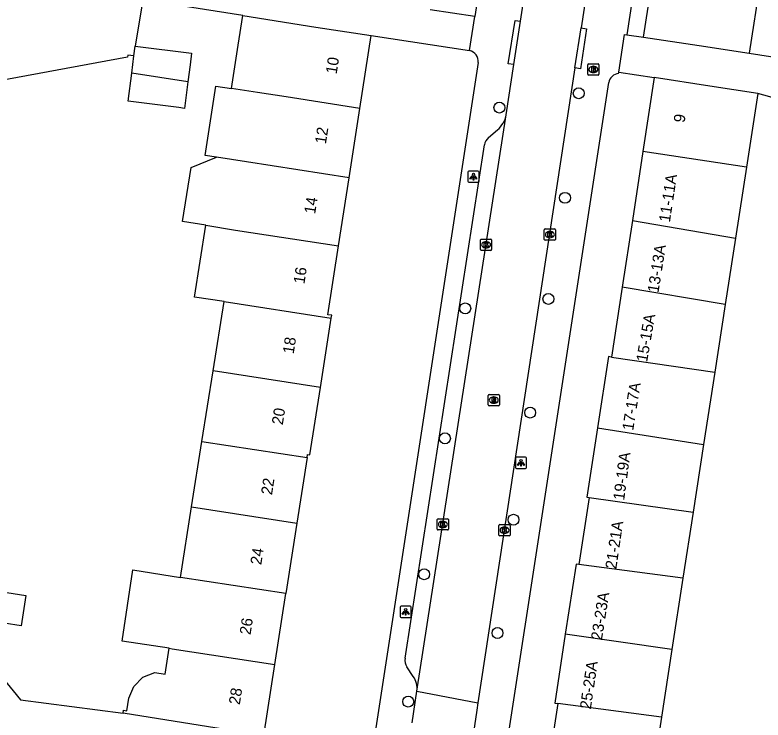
# Model space of a CAD drawing. Extents: x 161486 to 162249, y 379484 to 380829.
# Drawn here: x 162088.8 to 162155.5, y 380629.2 to 380692 of the extents above; entities that cross this region are included whole.
import ezdxf

# ---------------------------------------------------------------- set-up
doc = ezdxf.new("R2010")
doc.units = 0
for name, color, linetype in [('IMGEO_Boom', 7, 'Continuous'), ('IMGEO_Brandkraan', 7, 'Continuous'), ('IMGEO_Kolk', 7, 'Continuous'), ('IMGEO_Lichtpunt', 7, 'Continuous'), ('IMGEO_Pand', 7, 'Continuous'), ('IMGEO_Pand_nummerreeks', 7, 'Continuous'), ('IMGEO_Rijbaan_lokaal_open', 7, 'Continuous'), ('IMGEO_Rioolput', 7, 'Continuous'), ('IMGEO_Voetpad_open', 7, 'Continuous')]:
    doc.layers.add(name, color=color, linetype=linetype)

msp = doc.modelspace()

# ---------------------------------------------------------------- linework, layer by layer
at = {"layer": 'IMGEO_Boom'}
for centre in [(162139.097, 380685.045), (162132.026, 380683.767), (162137.87, 380675.72), (162136.396, 380666.708), (162128.975, 380665.857), (162134.768, 380656.575), (162127.167, 380654.275), (162133.28, 380647.015), (162125.315, 380642.155), (162131.855, 380636.916), (162123.892, 380630.805)]:
    msp.add_circle(centre, 0.489, dxfattribs=at)
at = {"layer": 'IMGEO_Brandkraan'}
for p, q in [((162139.9, 380686.741), (162139.9, 380687.593)), ((162139.975, 380687.667), (162140.827, 380687.667)), ((162140.388, 380687.447), (162140.413, 380687.447)), ((162140.901, 380687.593), (162140.901, 380686.741)), ((162140.827, 380686.667), (162139.975, 380686.667)), ((162140.411, 380686.887), (162140.386, 380686.887))]:
    msp.add_line(p, q, dxfattribs=at)
for points in [[(162139.9, 380686.741), (162139.9, 380687.593)], [(162139.975, 380687.667), (162140.827, 380687.667)], [(162140.248, 380687.367), (162140.248, 380686.967), (162140.461, 380686.967)], [(162140.479, 380687.367), (162140.248, 380687.367)], [(162140.427, 380687.286), (162140.373, 380687.286), (162140.373, 380687.21)], [(162140.373, 380687.21), (162140.426, 380687.21)], [(162140.901, 380687.593), (162140.901, 380686.741)], [(162140.827, 380686.667), (162139.975, 380686.667)], [(162140.435, 380687.134), (162140.373, 380687.134), (162140.373, 380687.053)], [(162140.373, 380687.053), (162140.435, 380687.053)]]:
    msp.add_lwpolyline(points, dxfattribs=at)
for centre, radius, start, end in [((162139.977, 380687.591), 0.0765, 91.55205, 178.44795), ((162139.977, 380687.591), 0.0765, 91.55205, 178.44795), ((162140.428, 380687.248), 0.0379, 267.82845, 90.93552), ((162140.483, 380687.222), 0.145, 59.4692, 91.53667), ((162140.508, 380687.269), 0.0922, 285.51372, 58.15012), ((162140.825, 380687.591), 0.0765, 1.55205, 88.44795), ((162140.825, 380687.591), 0.0765, 1.55205, 88.44795), ((162139.977, 380686.743), 0.0765, 181.55205, 268.44795), ((162139.977, 380686.743), 0.0765, 181.55205, 268.44795), ((162140.436, 380687.093), 0.0404, 269.87594, 90.50774), ((162140.467, 380687.218), 0.251, 268.66757, 293.53466), ((162140.513, 380687.077), 0.105, 301.31148, 78.98903), ((162140.825, 380686.743), 0.0765, 271.55205, 358.44795), ((162140.825, 380686.743), 0.0765, 271.55205, 358.44795)]:
    msp.add_arc(centre, radius, start, end, dxfattribs=at)
for centre, major_axis, ratio, start_param, end_param in [((162140.387, 380687.167), (-0.387, 0.002), 0.722429, 4.712389, 7.853982), ((162140.412, 380687.167), (-0.39, 0.002), 0.717154, 1.570796, 4.712389)]:
    msp.add_ellipse(centre, major_axis=major_axis, ratio=ratio, start_param=start_param, end_param=end_param, dxfattribs=at)
at = {"layer": 'IMGEO_Kolk'}
for p, q in [((162136.024, 380672.017), (162136.024, 380672.869)), ((162136.099, 380672.943), (162136.951, 380672.943)), ((162136.512, 380672.723), (162136.537, 380672.723)), ((162137.025, 380672.869), (162137.025, 380672.017)), ((162130.332, 380671.109), (162130.332, 380671.961)), ((162130.407, 380672.035), (162131.259, 380672.035)), ((162131.333, 380671.961), (162131.333, 380671.109)), ((162136.951, 380671.943), (162136.099, 380671.943)), ((162136.535, 380672.163), (162136.51, 380672.163)), ((162130.843, 380671.255), (162130.818, 380671.255)), ((162130.82, 380671.815), (162130.845, 380671.815)), ((162131.259, 380671.035), (162130.407, 380671.035)), ((162126.482, 380646.178), (162126.482, 380647.03)), ((162126.557, 380647.104), (162127.409, 380647.104)), ((162126.97, 380646.884), (162126.995, 380646.884)), ((162127.483, 380647.03), (162127.483, 380646.178)), ((162131.979, 380645.656), (162131.979, 380646.508)), ((162132.054, 380646.582), (162132.906, 380646.582)), ((162132.98, 380646.508), (162132.98, 380645.656)), ((162127.409, 380646.104), (162126.557, 380646.104)), ((162126.993, 380646.324), (162126.968, 380646.324)), ((162132.467, 380646.362), (162132.492, 380646.362)), ((162132.906, 380645.582), (162132.054, 380645.582)), ((162132.49, 380645.802), (162132.465, 380645.802))]:
    msp.add_line(p, q, dxfattribs=at)
for points in [[(162136.024, 380672.017), (162136.024, 380672.869)], [(162136.099, 380672.943), (162136.951, 380672.943)], [(162136.345, 380672.643), (162136.468, 380672.643), (162136.468, 380672.492), (162136.598, 380672.643), (162136.762, 380672.643), (162136.616, 380672.492), (162136.769, 380672.243), (162136.617, 380672.243), (162136.532, 380672.407), (162136.468, 380672.34), (162136.468, 380672.243), (162136.345, 380672.243), (162136.345, 380672.643)], [(162137.025, 380672.869), (162137.025, 380672.017)], [(162130.332, 380671.109), (162130.332, 380671.961)], [(162130.407, 380672.035), (162131.259, 380672.035)], [(162131.333, 380671.961), (162131.333, 380671.109)], [(162136.951, 380671.943), (162136.099, 380671.943)], [(162130.653, 380671.735), (162130.776, 380671.735), (162130.776, 380671.584), (162130.906, 380671.735), (162131.07, 380671.735), (162130.924, 380671.584), (162131.077, 380671.335), (162130.925, 380671.335), (162130.84, 380671.499), (162130.776, 380671.432), (162130.776, 380671.335), (162130.653, 380671.335), (162130.653, 380671.735)], [(162131.259, 380671.035), (162130.407, 380671.035)], [(162126.482, 380646.178), (162126.482, 380647.03)], [(162126.557, 380647.104), (162127.409, 380647.104)], [(162126.803, 380646.804), (162126.926, 380646.804), (162126.926, 380646.653), (162127.056, 380646.804), (162127.22, 380646.804), (162127.074, 380646.653), (162127.227, 380646.404), (162127.075, 380646.404), (162126.99, 380646.568), (162126.926, 380646.501), (162126.926, 380646.404), (162126.803, 380646.404), (162126.803, 380646.804)], [(162127.483, 380647.03), (162127.483, 380646.178)], [(162131.979, 380645.656), (162131.979, 380646.508)], [(162132.054, 380646.582), (162132.906, 380646.582)], [(162132.98, 380646.508), (162132.98, 380645.656)], [(162127.409, 380646.104), (162126.557, 380646.104)], [(162132.3, 380646.282), (162132.423, 380646.282), (162132.423, 380646.131), (162132.553, 380646.282), (162132.717, 380646.282), (162132.571, 380646.131), (162132.724, 380645.882), (162132.572, 380645.882), (162132.487, 380646.046), (162132.423, 380645.979), (162132.423, 380645.882), (162132.3, 380645.882), (162132.3, 380646.282)], [(162132.906, 380645.582), (162132.054, 380645.582)]]:
    msp.add_lwpolyline(points, dxfattribs=at)
for centre, start, end in [((162136.101, 380672.867), 91.55205, 178.44795), ((162136.101, 380672.867), 91.55205, 178.44795), ((162136.949, 380672.867), 1.55205, 88.44795), ((162136.949, 380672.867), 1.55205, 88.44795), ((162130.409, 380671.959), 91.55205, 178.44795), ((162130.409, 380671.959), 91.55205, 178.44795), ((162131.257, 380671.959), 1.55205, 88.44795), ((162131.257, 380671.959), 1.55205, 88.44795), ((162136.101, 380672.019), 181.55205, 268.44795), ((162136.101, 380672.019), 181.55205, 268.44795), ((162136.949, 380672.019), 271.55205, 358.44795), ((162136.949, 380672.019), 271.55205, 358.44795), ((162130.409, 380671.111), 181.55205, 268.44795), ((162130.409, 380671.111), 181.55205, 268.44795), ((162131.257, 380671.111), 271.55205, 358.44795), ((162131.257, 380671.111), 271.55205, 358.44795), ((162126.559, 380647.028), 91.55205, 178.44795), ((162126.559, 380647.028), 91.55205, 178.44795), ((162127.407, 380647.028), 1.55205, 88.44795), ((162127.407, 380647.028), 1.55205, 88.44795), ((162132.056, 380646.506), 91.55205, 178.44795), ((162132.056, 380646.506), 91.55205, 178.44795), ((162132.904, 380646.506), 1.55205, 88.44795), ((162132.904, 380646.506), 1.55205, 88.44795), ((162126.559, 380646.18), 181.55205, 268.44795), ((162126.559, 380646.18), 181.55205, 268.44795), ((162127.407, 380646.18), 271.55205, 358.44795), ((162127.407, 380646.18), 271.55205, 358.44795), ((162132.056, 380645.658), 181.55205, 268.44795), ((162132.056, 380645.658), 181.55205, 268.44795), ((162132.904, 380645.658), 271.55205, 358.44795), ((162132.904, 380645.658), 271.55205, 358.44795)]:
    msp.add_arc(centre, 0.0765, start, end, dxfattribs=at)
for centre, major_axis, ratio, start_param, end_param in [((162136.511, 380672.443), (-0.387, 0.002), 0.722429, 4.712389, 7.853982), ((162136.536, 380672.443), (-0.39, 0.002), 0.717154, 1.570796, 4.712389), ((162130.819, 380671.535), (-0.387, 0.002), 0.722429, 4.712389, 7.853982), ((162130.844, 380671.535), (-0.39, 0.002), 0.717154, 1.570796, 4.712389), ((162126.969, 380646.604), (-0.387, 0.002), 0.722429, 4.712389, 7.853982), ((162126.994, 380646.604), (-0.39, 0.002), 0.717154, 1.570796, 4.712389), ((162132.466, 380646.082), (-0.387, 0.002), 0.722429, 4.712389, 7.853982), ((162132.491, 380646.082), (-0.39, 0.002), 0.717154, 1.570796, 4.712389)]:
    msp.add_ellipse(centre, major_axis=major_axis, ratio=ratio, start_param=start_param, end_param=end_param, dxfattribs=at)
at = {"layer": 'IMGEO_Lichtpunt'}
for p, q in [((162129.213, 380678.015), (162129.213, 380677.208)), ((162129.213, 380678.015), (162129.213, 380677.208)), ((162130.115, 380678.11), (162129.307, 380678.11)), ((162130.115, 380678.11), (162129.307, 380678.11)), ((162130.209, 380677.208), (162130.209, 380678.015)), ((162130.209, 380677.208), (162130.209, 380678.015)), ((162129.307, 380677.114), (162130.115, 380677.114)), ((162129.307, 380677.114), (162130.115, 380677.114)), ((162134.354, 380652.589), (162133.546, 380652.589)), ((162134.354, 380652.589), (162133.546, 380652.589)), ((162133.452, 380652.494), (162133.452, 380651.687)), ((162133.452, 380652.494), (162133.452, 380651.687)), ((162134.448, 380651.687), (162134.448, 380652.494)), ((162134.448, 380651.687), (162134.448, 380652.494)), ((162133.546, 380651.593), (162134.354, 380651.593)), ((162133.546, 380651.593), (162134.354, 380651.593)), ((162123.171, 380639.209), (162123.171, 380638.402)), ((162123.171, 380639.209), (162123.171, 380638.402)), ((162124.073, 380639.304), (162123.265, 380639.304)), ((162124.073, 380639.304), (162123.265, 380639.304)), ((162124.167, 380638.402), (162124.167, 380639.209)), ((162124.167, 380638.402), (162124.167, 380639.209)), ((162123.265, 380638.308), (162124.073, 380638.308)), ((162123.265, 380638.308), (162124.073, 380638.308))]:
    msp.add_line(p, q, dxfattribs=at)
for points in [[(162129.587, 380677.679), (162129.626, 380677.651), (162129.438, 380677.389), (162129.4, 380677.416), (162129.587, 380677.679)], [(162129.689, 380677.631), (162129.736, 380677.631), (162129.736, 380677.309), (162129.689, 380677.309), (162129.689, 380677.631)], [(162129.799, 380677.651), (162129.837, 380677.678), (162130.024, 380677.416), (162129.985, 380677.388), (162129.799, 380677.651)], [(162133.826, 380652.158), (162133.865, 380652.13), (162133.677, 380651.868), (162133.639, 380651.895), (162133.826, 380652.158)], [(162133.928, 380652.11), (162133.975, 380652.11), (162133.975, 380651.788), (162133.928, 380651.788), (162133.928, 380652.11)], [(162134.038, 380652.13), (162134.076, 380652.157), (162134.263, 380651.895), (162134.224, 380651.867), (162134.038, 380652.13)], [(162123.545, 380638.873), (162123.584, 380638.845), (162123.396, 380638.583), (162123.358, 380638.61), (162123.545, 380638.873)], [(162123.647, 380638.825), (162123.694, 380638.825), (162123.694, 380638.503), (162123.647, 380638.503), (162123.647, 380638.825)], [(162123.757, 380638.845), (162123.795, 380638.872), (162123.982, 380638.61), (162123.943, 380638.582), (162123.757, 380638.845)]]:
    msp.add_lwpolyline(points, dxfattribs=at)
for centre in [(162129.712, 380677.813), (162133.951, 380652.292), (162123.67, 380639.007)]:
    msp.add_circle(centre, 0.0994, dxfattribs=at)
for centre, start, end in [((162129.307, 380678.015), 90, 180), ((162129.307, 380678.015), 90, 180), ((162130.115, 380678.015), 0, 90), ((162130.115, 380678.015), 0, 90), ((162129.307, 380677.208), 180, 270), ((162129.307, 380677.208), 180, 270), ((162130.115, 380677.208), 270, 0), ((162130.115, 380677.208), 270, 360), ((162133.546, 380652.494), 90, 180), ((162133.546, 380652.494), 90, 180), ((162134.354, 380652.494), 0, 90), ((162134.354, 380652.494), 0, 90), ((162133.546, 380651.687), 180, 270), ((162133.546, 380651.687), 180, 270), ((162134.354, 380651.687), 270, 0), ((162134.354, 380651.687), 270, 360), ((162123.265, 380639.209), 90, 180), ((162123.265, 380639.209), 90, 180), ((162124.073, 380639.209), 0, 90), ((162124.073, 380639.209), 0, 90), ((162123.265, 380638.402), 180, 270), ((162123.265, 380638.402), 180, 270), ((162124.073, 380638.402), 270, 0), ((162124.073, 380638.402), 270, 360)]:
    msp.add_arc(centre, 0.0946, start, end, dxfattribs=at)
at = {"layer": 'IMGEO_Pand'}
for points in [[(162144.881, 380690.039), (162145.841, 380696.382)], [(162155.266, 380694.952), (162154.307, 380688.613)], [(162108.126, 380685.46), (162108.741, 380689.335), (162109.161, 380691.982)], [(162109.161, 380691.982), (162115.653, 380690.951), (162120.592, 380690.18)], [(162119.588, 380683.698), (162120.592, 380690.18)], [(162144.881, 380690.039), (162149.825, 380689.291), (162154.307, 380688.613)], [(162099.442, 380688.377), (162099.551, 380689.244)], [(162099.551, 380689.244), (162104.578, 380688.611), (162104.449, 380687.588), (162104.256, 380686.056)], [(162099.247, 380686.826), (162099.442, 380688.377)], [(162104.256, 380686.056), (162103.959, 380683.696), (162103.439, 380683.762), (162098.933, 380684.328), (162099.247, 380686.826)], [(162104.256, 380686.056), (162099.247, 380686.826)], [(162145.834, 380686.435), (162144.825, 380679.855)], [(162155.068, 380685.012), (162150.778, 380685.677), (162145.834, 380686.435)], [(162106.787, 380679.339), (162105.78, 380679.494), (162106.73, 380685.675), (162108.126, 380685.46)], [(162119.588, 380683.698), (162112.996, 380684.712), (162110.445, 380685.104), (162108.126, 380685.46)], [(162155.068, 380685.012), (162154.055, 380678.46)], [(162118.631, 380677.517), (162119.588, 380683.698)], [(162144.825, 380679.855), (162143.881, 380673.705)], [(162154.055, 380678.46), (162144.825, 380679.855)], [(162105.841, 380673.272), (162103.764, 380673.602), (162104.531, 380678.434), (162106.787, 380679.339)], [(162118.631, 380677.517), (162109.464, 380678.927), (162106.787, 380679.339)], [(162154.055, 380678.46), (162153.076, 380672.126)], [(162117.69, 380671.437), (162118.631, 380677.517)], [(162107.486, 380666.465), (162104.826, 380666.874), (162105.841, 380673.272)], [(162105.841, 380673.272), (162108.499, 380672.85), (162117.69, 380671.437)], [(162143.881, 380673.705), (162142.969, 380667.758)], [(162143.881, 380673.705), (162153.076, 380672.126)], [(162153.076, 380672.126), (162152.163, 380666.219)], [(162117.031, 380664.998), (162117.07, 380665.249), (162116.74, 380665.301), (162117.69, 380671.437)], [(162142.969, 380667.758), (162142.012, 380661.522)], [(162152.163, 380666.219), (162142.969, 380667.758)], [(162106.504, 380660.282), (162107.486, 380666.465)], [(162107.486, 380666.465), (162117.031, 380664.998)], [(162152.163, 380666.219), (162151.228, 380660.176)], [(162116.066, 380658.812), (162117.031, 380664.998)], [(162142.012, 380661.522), (162141.756, 380661.56), (162140.78, 380655.201)], [(162142.012, 380661.522), (162151.228, 380660.176)], [(162105.506, 380653.997), (162106.504, 380660.282)], [(162116.066, 380658.812), (162106.504, 380660.282)], [(162151.228, 380660.176), (162150.232, 380653.731)], [(162114.876, 380652.556), (162114.922, 380652.849), (162115.131, 380652.818), (162116.066, 380658.812)], [(162140.78, 380655.201), (162139.832, 380649.023), (162140.029, 380648.993)], [(162140.78, 380655.201), (162150.232, 380653.731)], [(162104.58, 380648.164), (162105.506, 380653.997)], [(162105.506, 380653.997), (162114.876, 380652.556)], [(162150.232, 380653.731), (162149.3, 380647.702)], [(162114.876, 380652.556), (162113.965, 380646.721)], [(162140.029, 380648.993), (162139.113, 380643.031)], [(162140.029, 380648.993), (162149.3, 380647.702)], [(162103.583, 380641.881), (162104.58, 380648.164)], [(162104.58, 380648.164), (162113.965, 380646.721)], [(162149.3, 380647.702), (162148.389, 380641.805)], [(162113.965, 380646.721), (162112.984, 380640.435)], [(162102.579, 380635.556), (162098.373, 380636.202), (162099.348, 380642.543), (162103.583, 380641.881)], [(162139.113, 380643.031), (162138.857, 380643.07), (162137.896, 380636.808)], [(162148.389, 380641.805), (162139.113, 380643.031)], [(162112.984, 380640.435), (162103.583, 380641.881)], [(162081.206, 380638.975), (162081.599, 380641.535), (162082.995, 380641.321), (162089.804, 380640.275), (162089.388, 380637.569), (162086.323, 380638.04)], [(162148.389, 380641.805), (162147.406, 380635.453)], [(162111.997, 380634.109), (162112.984, 380640.435)], [(162137.896, 380636.808), (162136.954, 380630.668), (162137.222, 380630.628)], [(162147.406, 380635.453), (162137.896, 380636.808)], [(162098.474, 380629.762), (162098.516, 380630.029), (162098.803, 380629.984), (162098.978, 380631.1), (162099.439, 380632.161), (162100.224, 380632.969), (162101.302, 380633.386), (162102.211, 380633.243), (162102.579, 380635.556)], [(162102.579, 380635.556), (162102.85, 380635.515), (162111.997, 380634.109)], [(162147.406, 380635.453), (162146.472, 380629.407)], [(162111.01, 380627.789), (162111.997, 380634.109)], [(162137.222, 380630.628), (162136.333, 380624.832)], [(162146.472, 380629.407), (162137.222, 380630.628)], [(162111.01, 380627.789), (162106.071, 380628.56), (162098.474, 380629.762)], [(162146.472, 380629.407), (162145.546, 380623.419)]]:
    msp.add_lwpolyline(points, dxfattribs=at)
at = {"layer": 'IMGEO_Rijbaan_lokaal_open'}
for points in [[(162133.908, 380691.46), (162135.128, 380699.472)], [(162140.517, 380698.694), (162139.304, 380690.868)], [(162109.161, 380691.982), (162100.238, 380693.398), (162099.551, 380689.244)], [(162129.827, 380691.875), (162125.845, 380692.495)], [(162129.355, 380688.847), (162129.827, 380691.875)], [(162133.3, 380687.594), (162133.908, 380691.46)], [(162138.753, 380687.297), (162139.304, 380690.868)], [(162120.592, 380690.18), (162129.355, 380688.847)], [(162142.667, 380686.916), (162143.178, 380690.285), (162143.388, 380690.241)], [(162143.388, 380690.241), (162144.881, 380690.039)], [(162154.307, 380688.613), (162162.472, 380687.354), (162168.673, 380687.672)], [(162099.442, 380688.377), (162098.896, 380688.446), (162098.873, 380688.264), (162085.474, 380685.795), (162084.811, 380685.895)], [(162138.753, 380687.297), (162130.113, 380630.707)], [(162132.628, 380683.134), (162133.3, 380687.594)], [(162142.667, 380686.916), (162145.834, 380686.435)], [(162167.701, 380681.656), (162166.26, 380681.9), (162155.068, 380685.012)], [(162124.671, 380631.722), (162132.628, 380683.134)], [(162086.323, 380638.04), (162085.87, 380635.161), (162089.333, 380630.951), (162098.474, 380629.762)], [(162124.242, 380628.91), (162124.671, 380631.722)], [(162124.671, 380631.722), (162130.113, 380630.707)], [(162130.113, 380630.707), (162130.012, 380630.045), (162129.701, 380628.045)]]:
    msp.add_lwpolyline(points, dxfattribs=at)
at = {"layer": 'IMGEO_Rioolput'}
for p, q in [((162131.023, 380657.258), (162131.023, 380658.11)), ((162131.098, 380658.184), (162131.95, 380658.184)), ((162131.511, 380657.964), (162131.536, 380657.964)), ((162132.024, 380658.11), (162132.024, 380657.258)), ((162131.95, 380657.184), (162131.098, 380657.184)), ((162131.534, 380657.404), (162131.509, 380657.404))]:
    msp.add_line(p, q, dxfattribs=at)
for points in [[(162131.023, 380657.258), (162131.023, 380658.11)], [(162131.098, 380658.184), (162131.95, 380658.184)], [(162131.612, 380657.882), (162131.36, 380657.884), (162131.36, 380657.484)], [(162132.024, 380658.11), (162132.024, 380657.258)], [(162131.95, 380657.184), (162131.098, 380657.184)], [(162131.36, 380657.484), (162131.484, 380657.484), (162131.484, 380657.646), (162131.495, 380657.646)], [(162131.538, 380657.803), (162131.484, 380657.803), (162131.484, 380657.722)], [(162131.484, 380657.722), (162131.536, 380657.722)], [(162131.542, 380657.617), (162131.613, 380657.484), (162131.753, 380657.484), (162131.688, 380657.61)]]:
    msp.add_lwpolyline(points, dxfattribs=at)
for centre, radius, start, end in [((162131.1, 380658.108), 0.0765, 91.55205, 178.44795), ((162131.1, 380658.108), 0.0765, 91.55205, 178.44795), ((162131.611, 380657.772), 0.109, 350.36119, 89.41601), ((162131.948, 380658.108), 0.0765, 1.55205, 88.44795), ((162131.948, 380658.108), 0.0765, 1.55205, 88.44795), ((162131.1, 380657.26), 0.0765, 181.55205, 268.44795), ((162131.1, 380657.26), 0.0765, 181.55205, 268.44795), ((162131.494, 380657.593), 0.0533, 26.02933, 88.69889), ((162131.52, 380657.911), 0.19, 274.7715, 282.96867), ((162131.544, 380657.707), 0.0964, 77.00612, 93.18647), ((162131.558, 380657.764), 0.0378, 276.66336, 79.67722), ((162131.609, 380657.772), 0.112, 277.58423, 350.98172), ((162131.593, 380657.557), 0.108, 29.51342, 73.79051), ((162131.948, 380657.26), 0.0765, 271.55205, 358.44795), ((162131.948, 380657.26), 0.0765, 271.55205, 358.44795)]:
    msp.add_arc(centre, radius, start, end, dxfattribs=at)
for centre, major_axis, ratio, start_param, end_param in [((162131.51, 380657.684), (-0.387, 0.002), 0.722429, 4.712389, 7.853982), ((162131.535, 380657.684), (-0.39, 0.002), 0.717154, 1.570796, 4.712389)]:
    msp.add_ellipse(centre, major_axis=major_axis, ratio=ratio, start_param=start_param, end_param=end_param, dxfattribs=at)
at = {"layer": 'IMGEO_Voetpad_open'}
for points in [[(162140.304, 380759.987), (162138.778, 380750), (162133.605, 380716.139), (162129.827, 380691.875)], [(162153.828, 380758.083), (162152.56, 380750), (162147.249, 380715.624), (162143.388, 380690.241)], [(162133.3, 380687.594), (162132.807, 380687.671), (162133.415, 380691.537), (162133.908, 380691.46)], [(162139.304, 380690.868), (162139.798, 380690.792), (162139.247, 380687.221), (162138.753, 380687.297)], [(162130.126, 380687.774), (162120.698, 380626.536)], [(162142.65, 380686.805), (162142.667, 380686.916)], [(162126.826, 380588.847), (162141.781, 380685.99)], [(162131.063, 380681.09), (162131.855, 380681.772)], [(162123.62, 380634.67), (162130.681, 380680.433)], [(162124.348, 380633.053), (162123.78, 380633.889)]]:
    msp.add_lwpolyline(points, dxfattribs=at)
for centre, radius, start, end in [((162129.184, 380687.911), 0.952, 351.75243, 79.64555), ((162142.719, 380685.861), 0.947, 94.18579, 172.14092), ((162130.308, 380683.55), 2.357, 311.01594, 349.8301), ((162131.671, 380680.297), 1, 127.48272, 172.16721), ((162124.64, 380634.472), 1.039, 169.01266, 214.1428), ((162122.684, 380631.944), 2, 353.61531, 33.66578)]:
    msp.add_arc(centre, radius, start, end, dxfattribs=at)

# ---------------------------------------------------------------- texts
at = {"layer": 'IMGEO_Pand_nummerreeks'}
for s, rotation, p in [('10', 81.26833, (162117.512, 380686.719)), ('9', 81.27803, (162148.53, 380682.376)), ('12', 81.26833, (162116.552, 380680.474)), ('11-11A', 81.36658, (162147.224, 380673.496)), ('14', 81.26833, (162115.594, 380674.237)), ('13-13A', 80.99522, (162146.203, 380667.214)), ('16', 81.26833, (162114.636, 380667.998)), ('15-15A', 80.14692, (162145.193, 380661.036)), ('18', 81.26874, (162113.679, 380661.762)), ('17-17A', 80.90972, (162143.95, 380654.919)), ('20', 81.26874, (162112.707, 380655.433)), ('19-19A', 82.36667, (162143.147, 380648.709)), ('22', 81.26874, (162111.747, 380649.188)), ('21-21A', 81.61675, (162142.445, 380642.577)), ('24', 81.26874, (162110.789, 380642.952)), ('23-23A', 81.11934, (162141.161, 380636.224)), ('26', 81.26833, (162109.831, 380636.713)), ('25-25A', 81.66002, (162140.176, 380630.081)), ('28', 81.26874, (162108.874, 380630.477))]:
    msp.add_text(s, height=1, rotation=rotation, dxfattribs=at).set_placement(p)

doc.saveas('drawing.dxf')
